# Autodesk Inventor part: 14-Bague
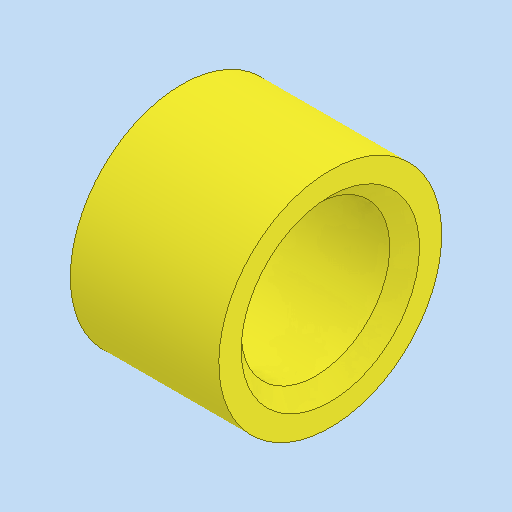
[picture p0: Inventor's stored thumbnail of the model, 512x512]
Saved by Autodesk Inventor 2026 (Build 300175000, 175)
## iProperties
Created: 2025-12
Part Number: 14-Bague
Material: Générique
Document SubType Name: Modeling
Designer: thierry.jost
Density: 1 g/cm^3
Appearance: Jaune canari
Author: thierry.jost
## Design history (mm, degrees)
sketch "Esquisse1"
  geometry: C1 r 5 at (0, 0); C2 r 7.5 at (0, 0); 1 further point
  constraints: 2 centre point, 2 coincident
  dimensions: "d0" = 15 diameter of C2; "d1" = 10 diameter of C1
extrude "Extrusion1" new body sketch "Esquisse1" distance "d2" = 10; taper "d3" = 0 deg
chamfer "Chanfrein1" distance "d4" = 1; stored, may be unused: second distance "d5" = 2, angle "d6" = 45 deg
node "Solide1"
